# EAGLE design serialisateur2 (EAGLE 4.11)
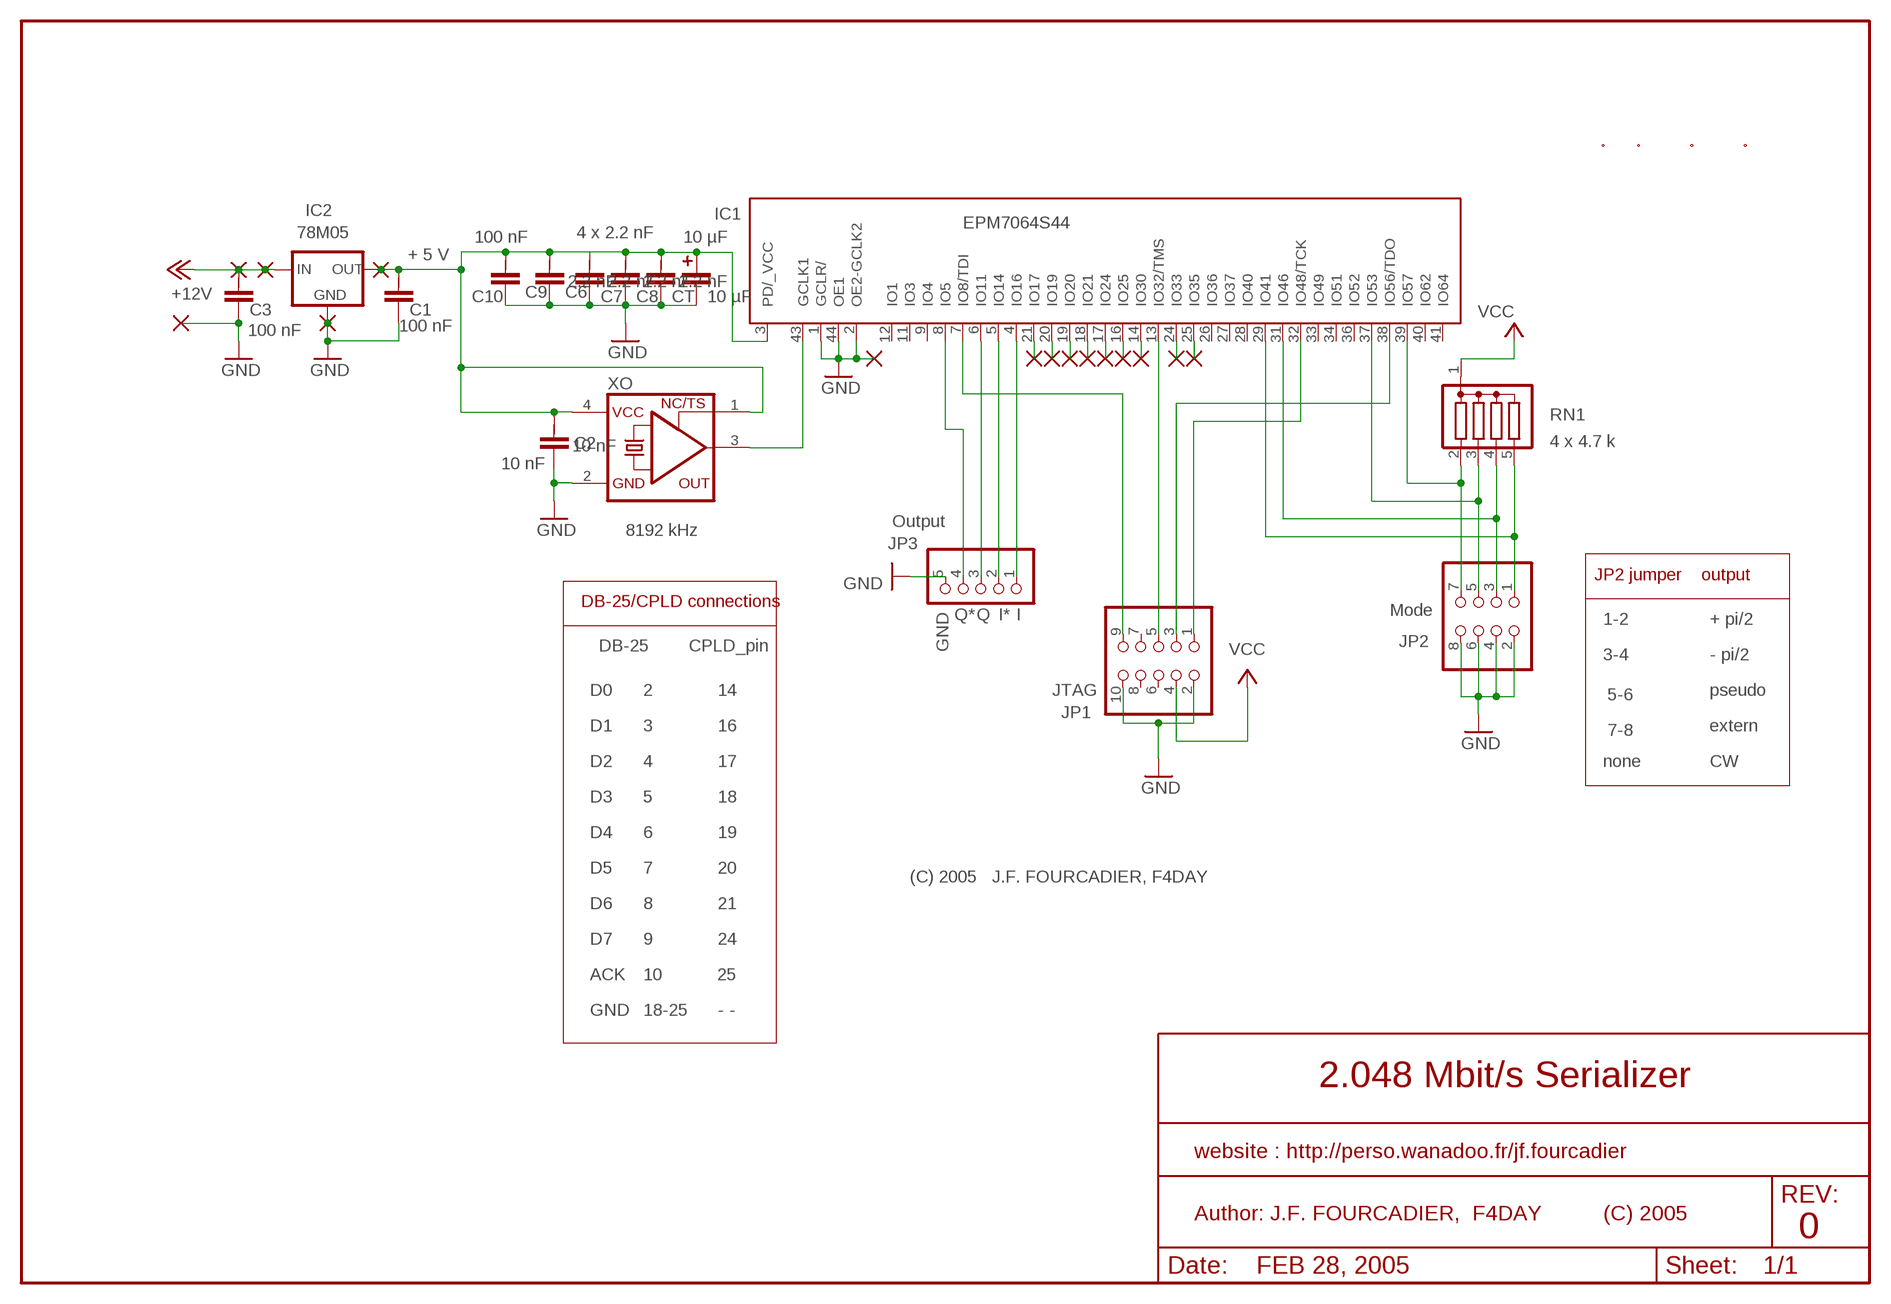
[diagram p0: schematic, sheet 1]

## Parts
#2  PAD-S  [2,54/0,4]
#3  PAD-S  [2,54/0,4]
#4  PAD-S  [2,54/0,4]
#5  PAD-S  [2,54/0,4]
#6  PAD-S  [2,54/0,4]
#7  #7  PAD-S  [2,54/0,4]
#8  #8  PAD-S  [2,54/0,4]
#9  PAD-S  [2,54/0,4]
#10  PAD-S  [2,54/0,4]
#18  PAD-S  [2,54/0,4]
C1  C1206  [C1206]
C2  10 nF  C1206  [C1206]
C3  C1206  [C1206]
C6  2.2 nF  C1206  [C1206]
C7  2.2 nF  C1206  [C1206]
C8  2.2 nF  C1206  [C1206]
C9  2.2 nF  C1206  [C1206]
C10  100 nF  C1206  [C1206]
CT  10 µF  CT6032  [CT6032]
IC1  EPM7064S44  EPM7064S44_2  [PLCC-S44_2]
IC2  78M05  78XXL  [78XXL]
JP1  PINHD-2X5  [2X05]
JP2  PINHD-2X4  [2X04]
JP3  PINHD-1X5D  [1X05]
RN1  G04R  [SIL5]
U$1  TROU_FIX  [TROU_FIX]
U$2  TROU_FIX  [TROU_FIX]
U$3  TROU_FIX  [TROU_FIX]
U$4  TROU_FIX  [TROU_FIX]
U$5  PAD-S  [2,54/0,4]
U$6  PAD-S  [2,54/0,4]
U$7  PAD-S  [2,54/0,4]
U$8  PAD-S  [2,54/0,4]
U$9  PAD-S  [2,54/0,4]
XO  8192 kHz  XO-1100S  [1100S]

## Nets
+12V: C3.1 IC2.IN U$6.1(P) U$8.1(P)
GND: #18.1(P) C1.2 C2.2 C3.2 C6.2 C7.2 C8.2 C9.2 C10.2 CT.- IC1.1(GCLR/) IC1.2(OE2-GCLK2) IC1.44(OE1) IC2.GND JP1.2 JP1.10 JP2.2 JP2.4 JP2.6 JP2.8 JP3.5 U$7.1(P) U$9.1(P) XO.2(GND)
N$1: IC1.32(IO48/TCK) JP1.1
N$2: IC1.38(IO56/TDO) JP1.3
N$3: IC1.13(IO32/TMS) JP1.5
N$4: IC1.7(IO8/TDI) JP1.9
N$5: #2.1(P) IC1.14(IO30)
N$6: IC1.31(IO46) JP2.3 RN1.4
N$8: IC1.8(IO5) JP3.4
N$9: IC1.29(IO41) JP2.1 RN1.5
N$10: IC1.4(IO16) JP3.1
N$11: IC1.5(IO14) JP3.2
N$12: IC1.43(GCLK1) XO.3(OUT)
N$13: IC1.37(IO53) JP2.5 RN1.3
N$14: IC1.6(IO11) JP3.3
N$15: IC1.39(IO57) JP2.7 RN1.2
N$19: #3.1(P) IC1.16(IO25)
N$27: #4.1(P) IC1.17(IO24)
N$28: #5.1(P) IC1.18(IO21)
N$30: #6.1(P) IC1.19(IO20)
N$31: #7.1(P) IC1.20(IO19)
N$32: #8.1(P) IC1.21(IO17)
N$33: #9.1(P) IC1.24(IO33)
N$34: #10.1(P) IC1.25(IO35)
VCC: C1.1 C2.1 C6.1 C7.1 C8.1 C9.1 C10.1 CT.+ IC1.3(PD/_VCC) IC2.OUT JP1.4 RN1.1 U$5.1(P) XO.1(TS) XO.4(VCC)
Unconnected: IC1.9(IO4) IC1.11(IO3) IC1.12(IO1) IC1.26(IO36) IC1.27(IO37) IC1.28(IO40) IC1.33(IO49) IC1.34(IO51) IC1.36(IO52) IC1.40(IO62) IC1.41(IO64) JP1.6 JP1.7 JP1.8

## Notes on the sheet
- 4 x 2.2 nF | 10 µF
- + 5 V
- 100 nF | 100 nF
- 4 x 4.7 k
- 10 nF
- Output
- JP2 jumper    output
- DB-25/CPLD connections | GND
- Q* | Q | I* | I | Mode
- 1-2 | + pi/2
- DB-25        CPLD_pin
- 3-4 | - pi/2
- D0 | 2             14 | JTAG | 5-6 | pseudo
- D1 | 3             16 | 7-8 | extern
- D2 | 4             17 | none | CW
- D3 | 5             18
- D4 | 6             19
- D5 | 7             20
- (C) 2005   J.F. FOURCADIER, F4DAY
- D6 | 8             21
- D7 | 9             24
- ACK | 10           25
- GND | 18-25      - -
- 2.048 Mbit/s Serializer
- 0
- FEB 28, 2005

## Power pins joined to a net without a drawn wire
GND: IC1.10(GND) IC1.22(GND) IC1.30(GND) IC1.42(GND)
VCC: IC1.15(VCC) IC1.23(VCC) IC1.35(VCC)

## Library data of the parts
#2-#10 #18 U$5-U$9 = wirepad:PAD-S
C1-C3 C6-C10 = capacitor-smd:C
CT = capacitor-smd:CT
IC1 = altera:EPM7064: EPM7064 MAX 7000 family
IC2 = v-reg:78XXL: VOLTAGE REGULATOR
JP1 = pinhead:PINHD-2X5: PIN HEADER
JP2 = pinhead:PINHD-2X4: PIN HEADER
JP3 = pinhead:PINHD-1X5: PIN HEADER
RN1 = resistor-sil:G04R: SIL RESISTOR
U$1-U$4 = holes:TROU_FIX
XO = crystal:XO-: CRYSTAL

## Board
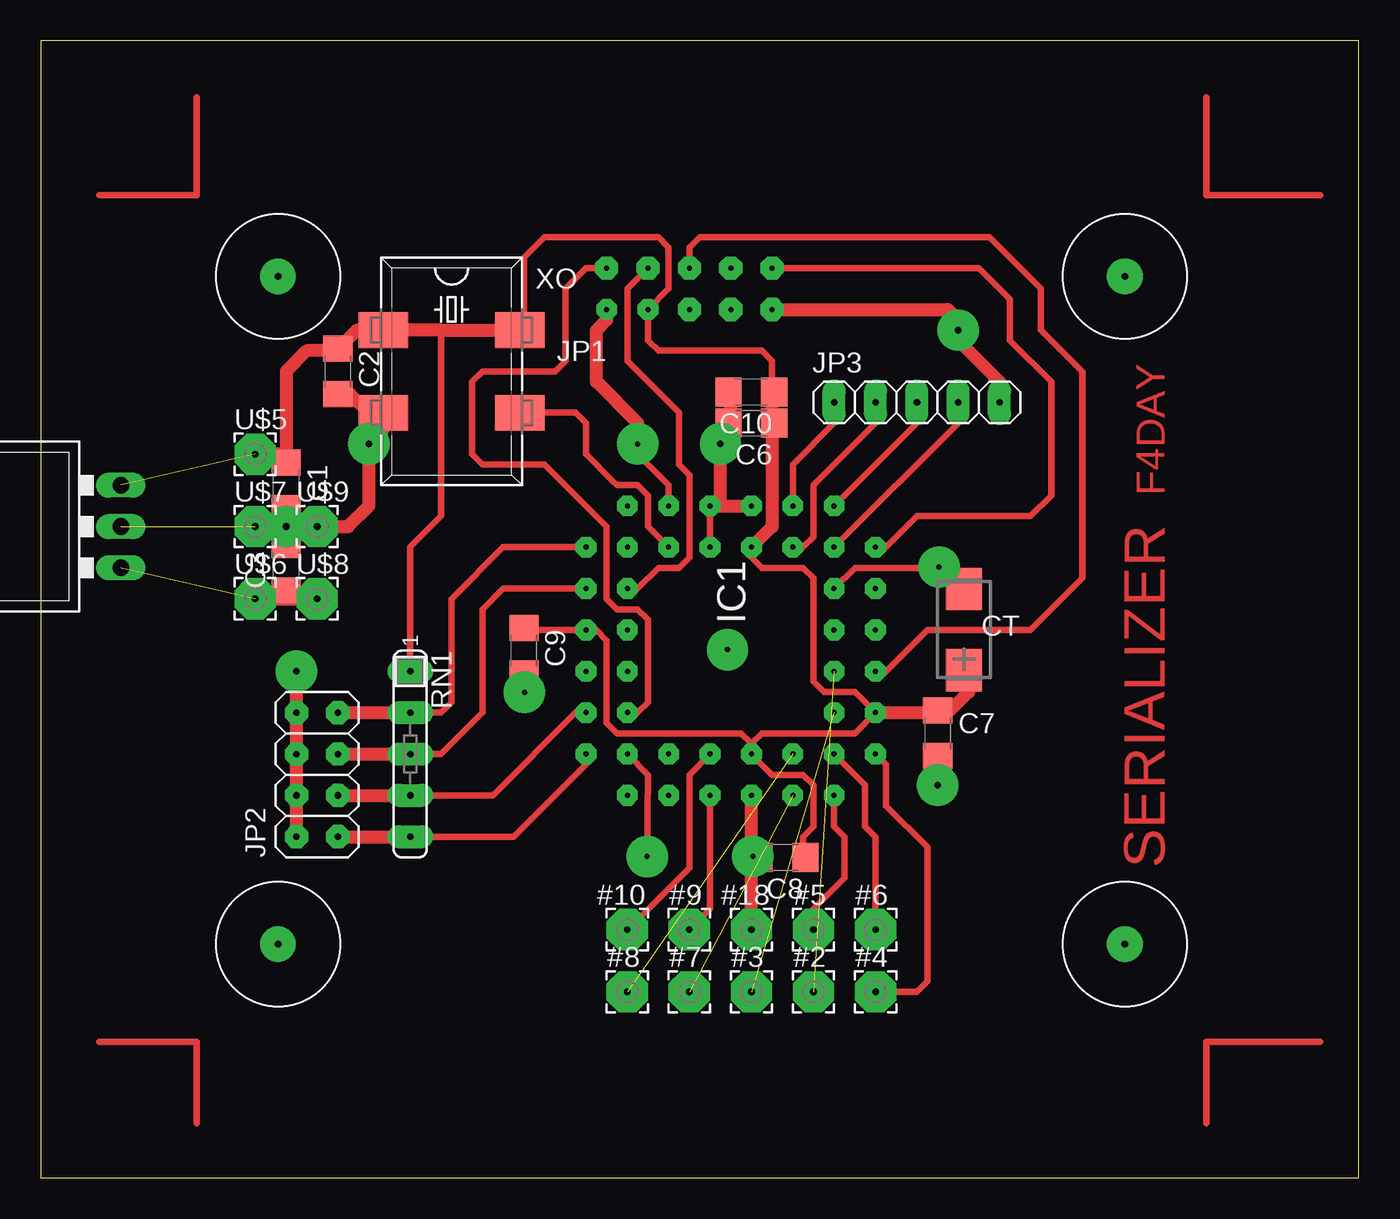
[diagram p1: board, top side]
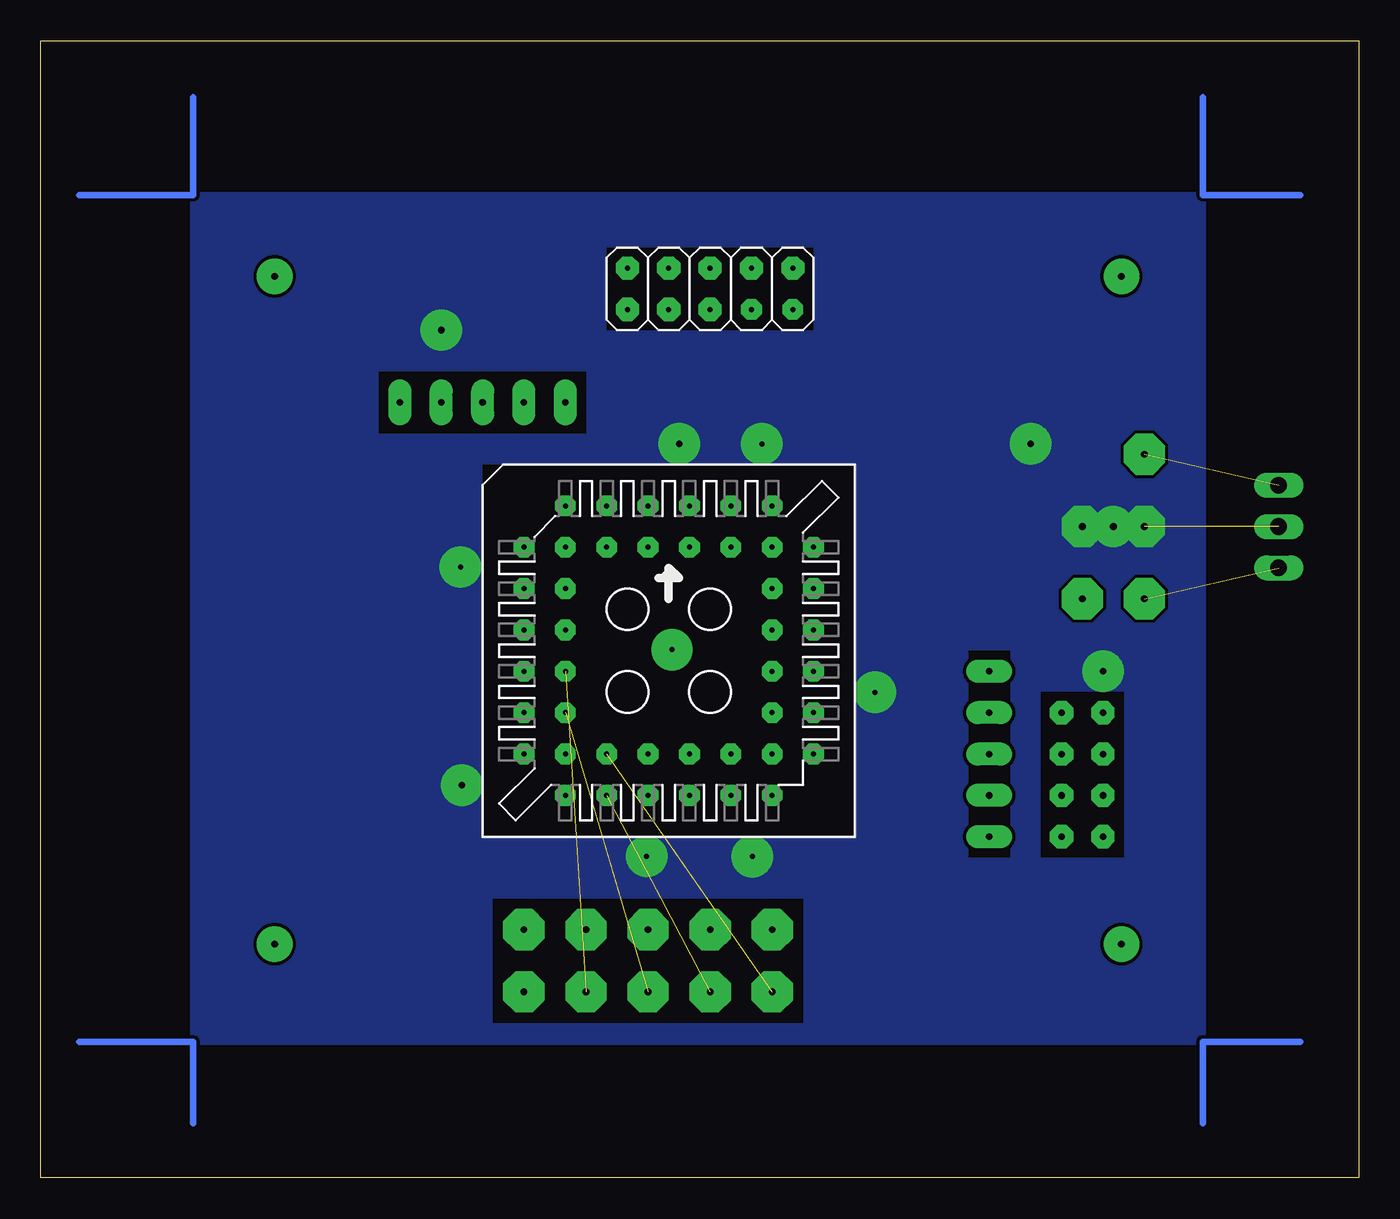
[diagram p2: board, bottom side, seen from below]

Size 80.95 x 69.84 mm. Coordinates in mm from the lower left corner, seen from the top.
Outline: 0,0 80.95,0 80.95,69.84 0,69.84 0,0
Copper layers (1*16): Top 0.035mm / dielectric 1.5mm / GND 0.035mm
Design rules "default": minimum track width 10mil, minimum drill 24mil, track to track 8mil, track to pad 8mil, pad to pad 8mil, via to via 8mil, smd to smd 8mil, copper to edge 40mil, drill to drill 8mil, minimum pad ring 10mil, minimum via ring 8mil, stop-mask expansion 4mil, vias tented up to drill 0mil, thermal gap 10mil
bRestrict: area 21.4,19.7 to 24,32.4; area 14.4,19.7 to 19.5,29.8; area 30.9,21 to 53.8,43.8; area 34.1,9.5 to 53.2,17.1; area 33.5,52.1 to 46.2,57.1; area 47.5,45.7 to 60.2,49.5

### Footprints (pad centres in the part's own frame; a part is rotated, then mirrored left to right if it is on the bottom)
2,54/0,4 = drill 0.406 pad 2.54 octagon: 1 0,0
C1206 = smd 1.6 x 1.8: 1 -1.4,0; 2 1.4,0
CT6032 = smd 2.6 x 2.2: + -2.5,0; - 2.5,0
PLCC-S44_2 = drill 0.305 pad 1.27 octagon: 1 1.27,6.35; 2 -1.27,8.89; 3 -1.27,6.35; 4 -3.81,8.89; 5 -3.81,6.35; 6 -6.35,8.89; 7 -8.89,6.35; 8 -6.35,6.35; 9 -8.89,3.81; 10 -6.35,3.81; 11 -8.89,1.27; 12 -6.35,1.27; 13 -8.89,-1.27; 14 -6.35,-1.27; 15 -8.89,-3.81; 16 -6.35,-3.81; 17 -8.89,-6.35; 18 -6.35,-8.89; 19 -6.35,-6.35; 20 -3.81,-8.89; 21 -3.81,-6.35; 22 -1.27,-8.89; 23 -1.27,-6.35; 24 1.27,-8.89; 25 1.27,-6.35; 26 3.81,-8.89; 27 3.81,-6.35; 28 6.35,-8.89; 29 8.89,-6.35; 30 6.35,-6.35; 31 8.89,-3.81; 32 6.35,-3.81; 33 8.89,-1.27; 34 6.35,-1.27; 35 8.89,1.27; 36 6.35,1.27; 37 8.89,3.81; 38 6.35,3.81; 39 8.89,6.35; 40 6.35,8.89; 41 6.35,6.35; 42 3.81,8.89; 43 3.81,6.35; 44 1.27,8.89
78XXL = drill 1.016 long: GND 0,-3.81; IN -2.54,-3.81; OUT 2.54,-3.81 | hole 3.302: 0,11.176
2X05 = drill 0.305 pad 1.422 octagon: 1 -5.08,-1.27; 3 -2.54,-1.27; 5 0,-1.27; 6 0,1.27; 7 2.54,-1.27; 8 2.54,1.27; 9 5.08,-1.27; 10 5.08,1.27 | drill 0.305 pad 1.27 octagon: 2 -5.08,1.27; 4 -2.54,1.27
2X04 = drill 0.406 pad 1.422 octagon: 1 -3.81,-1.27; 2 -3.81,1.27; 3 -1.27,-1.27; 4 -1.27,1.27; 5 1.27,-1.27; 6 1.27,1.27; 7 3.81,-1.27; 8 3.81,1.27
1X05 = drill 0.406 pad 1.422 long: 1 -5.08,0; 2 -2.54,0; 3 0,0; 4 2.54,0; 5 5.08,0
SIL5 = drill 0.406 pad 1.422 long: 1 -5.08,0; 2 -2.54,0; 3 0,0; 4 2.54,0; 5 5.08,0
TROU_FIX = drill 0.406 pad 2.184 round: P 0,0
1100S = smd 2.184 x 3.048: 1 -2.54,-4.191; 2 2.54,-4.191; 3 2.54,4.191; 4 -2.54,4.191

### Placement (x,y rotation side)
#2  47.46,11.42 0 top
#3  43.65,11.42 0 top
#4  51.27,11.42 0 top
#5  47.46,15.23 0 top
#6  51.27,15.23 0 top
#7  39.84,11.42 0 top
#8  36.03,11.42 0 top
#9  39.84,15.23 0 top
#10  36.03,15.23 0 top
#18  43.65,15.23 0 top
C1  15.08,42.54 270 top
C2  18.25,49.52 270 top
C3  15.08,37.46 90 top
C6  43.65,46.35 180 top
C7  55.08,27.3 270 top
C8  45.55,19.68 180 top
C9  29.68,32.38 270 top
C10  43.65,48.26 180 top
CT  56.7,33.67 90 top
GND  [DET_100]  16.98,40 0 top
IC1  42.38,32.38 0 bottom
IC2  1.11,40 90 top
JP1  39.84,54.6 180 bottom
JP2  16.98,24.76 90 top
JP3  53.81,47.62 0 top
RN1  22.7,26.03 270 top
U$1  14.58,14.36 0 top
U$2  14.58,55.36 0 top
U$3  66.58,14.36 0 top
U$4  66.58,55.36 0 top
U$5  13.17,44.45 0 top
U$6  13.17,35.55 0 top
U$7  13.17,40 0 top
U$8  16.98,35.55 0 top
U$9  16.98,40 0 top
U$11  [DET_100]  13.17,44.45 0 top
U$12  [DET_100]  13.17,40 0 top
U$13  [DET_100]  13.17,35.55 0 top
U$14  [DET_100]  16.98,35.55 0 top
XO  25.23,49.52 270 top

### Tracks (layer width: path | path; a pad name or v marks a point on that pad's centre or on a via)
+12V  (1 unrouted)
  Top 0.813: C3.1 15.08,35.55 U$6.1 U$8.1
GND  (via drill 0.3 pad 2.54, 0.41 pad 2.54)  (1 unrouted)
  Top 0.406: IC1.30 37.3,24.76 v37.25,19.73 | v36.66,45.08 36.66,44.45 38.57,42.54 IC1.42 | IC1.1 IC1.44 | v55.18,37.52 55.13,37.52 55.08,37.46 50,37.46 IC1.10
  Top 0.813: v15.71,31.11 JP2.8 JP2.6 JP2.4 JP2.2 | v15.08,40 C1.2 | v15.08,40 U$7.1 U$9.1 | C9.2 29.68,29.84 v29.7,29.82 | 43.65,19.68 IC1.22 | 43.65,19.68 43.71,19.74 v43.74,19.74 43.8,19.68 C8.2 44.28,19.68 | C2.2 19.02,48.12 20.16,46.98 XO.2 21.04,45.97 v20.16,45.08 20.16,41.27 18.88,40 U$9.1 | C10.2 42.38,48.12 42.38,46.35 | 42.38,46.35 C6.2 | 42.38,46.35 42.38,48.26 | 42.38,46.35 41.74,45.71 v41.74,45.08 | v41.74,45.08 42.38,45.71 | 41.74,41.27 IC1.2 | 41.74,41.27 v41.74,45.08 | IC1.44 41.74,41.27 | 55.08,26.03 C7.2 v55.08,24.12 | CT.- 55.41,37.46 55.08,37.46 | JP3.5 58.89,48.89 56.35,51.43 v56.35,52.06 56.35,52.7 55.72,53.34 JP1.10 | #18.1 43.65,19.68 | JP1.2 34.76,52.7 34.12,52.06 34.12,48.89 36.66,46.35 v36.66,45.08 | v15.08,40 U$9.1 | C3.2 v15.08,40
  pour GND: 9.58,60.36 9.58,8.36 71.58,8.36 71.58,60.36
N$1
  Top 0.406: IC1.32 36.66,28.57 37.3,29.2 37.3,34.28 36.66,34.92 35.39,34.92 34.76,35.55 34.76,40 30.95,43.81 27.14,43.81 26.5,44.45 26.5,48.89 27.14,49.52 31.59,49.52 32.22,50.16 32.22,51.43 32.22,54.6 33.49,55.88 JP1.1
N$2
  Top 0.406: IC1.38 36.66,36.19 37.93,37.46 39.2,37.46 39.84,38.09 39.84,43.17 39.2,43.81 39.2,46.98 36.03,50.16 36.03,54.6 JP1.3
N$3
  Top 0.406: IC1.13 51.91,31.11 54.45,33.65 60.8,33.65 63.97,36.83 63.97,49.52 61.43,52.06 61.43,54.6 58.25,57.78 40.48,57.78 39.84,57.14 JP1.5
N$4
  Top 0.406: JP1.9 57.62,55.88 59.52,53.97 59.52,51.43 62.06,48.89 62.06,41.91 60.8,40.63 53.81,40.63 51.91,38.73 IC1.7
N$5  (1 unrouted)
N$6
  Top 0.406: IC1.31 32.85,28.57 27.77,23.49 RN1.4
  Top 0.813: JP2.3 RN1.4
N$7
  GND 0.406: 3.58,60.36 9.58,60.36 9.58,66.36
N$8
  Top 0.406: IC1.8 56.35,46.35 JP3.4
N$9
  Top 0.406: IC1.29 33.49,25.39 29.05,20.95 RN1.5
  Top 0.813: JP2.1 RN1.5
N$10
  Top 0.406: JP3.1 48.73,46.35 46.19,43.81 IC1.4
N$11
  Top 0.406: IC1.5 46.82,38.73 47.46,39.37 47.46,42.54 51.27,46.35 JP3.2
N$12
  Top 0.406: IC1.43 37.3,40 37.3,41.91 36.66,42.54 35.39,42.54 35.12,42.81 35.11,42.81 33.49,44.45 33.49,46.35 32.85,46.98 XO.3
N$13
  Top 0.406: IC1.37 28.41,36.19 27.14,34.92 27.14,28.57 24.6,26.03 RN1.3
  Top 0.813: JP2.5 RN1.3
N$14
  Top 0.406: IC1.6 53.81,46.35 JP3.3
N$15
  Top 0.406: IC1.39 28.41,38.73 25.23,35.55 25.23,29.2 24.6,28.57 RN1.2
  Top 0.813: JP2.7 RN1.2
N$16
  Top 0.4: 71.58,66.36 71.58,60.36 78.58,60.36
N$17
  Top 0.4: 71.58,3.36 71.58,8.36 78.58,8.36
N$18
  GND 0.406: 71.58,66.36 71.58,60.36 78.58,60.36
N$19  (1 unrouted)
N$20
  GND 0.406: 71.58,3.36 71.58,8.36 78.58,8.36
N$21
  GND 0.406: 3.58,8.36 9.58,8.36 9.58,3.36
N$27
  Top 0.406: IC1.17 51.91,25.39 51.91,22.86 54.45,20.31 54.45,12.06 53.81,11.42 #4.1
N$28
  Top 0.406: IC1.18 48.73,21.59 49.36,20.95 49.36,18.41 47.46,16.5 #5.1
N$29  (via drill 0.3 pad 2.54)
  other vias: 42.18,32.44
N$30
  Top 0.406: IC1.19 50.63,24.12 50.63,21.59 51.27,20.95 #6.1
N$31  (1 unrouted)
N$32  (1 unrouted)
N$33
  Top 0.406: #9.1 41.11,16.5 IC1.24
N$34
  Top 0.406: IC1.25 39.84,24.76 39.84,19.04 #10.1
N$100
  Top 0.406: 9.58,66.36 9.58,60.36 3.58,60.36
N$101
  Top 0.4: 9.58,3.36 9.58,8.36 3.58,8.36
VCC  (1 unrouted)
  Top 0.406: C9.1 30.03,33.87 30.25,33.65 30.95,33.65 | C8.1 46.82,19.81 46.82,20.95 | 30.95,33.65 29.68,33.65 | 46.82,20.95 46.82,19.68 | 46.82,20.95 47.46,21.59 47.46,24.12 46.82,24.76 44.92,24.76 44,25.66 IC1.23 43.65,26.66 | 30.95,33.65 IC1.35 34.12,33.65 34.76,33.02 34.76,27.93 35.39,27.3 43.02,27.3 43.65,26.66 | CT.+ 56.98,30.88 56.98,29.84 | 43.65,26.66 44.28,27.3 50,27.3 IC1.15 | C7.1 54.95,28.57 IC1.15 | IC1.15 50,29.84 48.09,29.84 47.46,30.47 47.46,36.83 46.82,37.46 44.28,37.46 43.65,38.09 IC1.3 | 44.92,46.48 44.92,50.16 44.28,50.8 37.93,50.8 37.3,51.43 JP1.4 38.57,54.6 38.57,57.14 37.93,57.78 30.95,57.78 29.68,56.51 29.68,52.06 | RN1.1 22.7,38.73 24.6,40.63 24.6,52.06
  Top 0.813: 56.76,31.11 56.98,31.11 56.98,29.84 55.72,28.57 IC1.15 | IC1.3 44.92,40 44.92,46.35 | C10.1 44.92,48.12 44.92,46.48 44.92,46.35 | 44.92,46.35 C6.1 | 29.68,52.06 XO.4 24.6,52.06 XO.1 19.39,52.06 C2.1 18.25,50.8 16.34,50.8 15.08,49.52 C1.1 15.08,44.45 U$5.1

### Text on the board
Top: F4DAY | SERIALIZER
